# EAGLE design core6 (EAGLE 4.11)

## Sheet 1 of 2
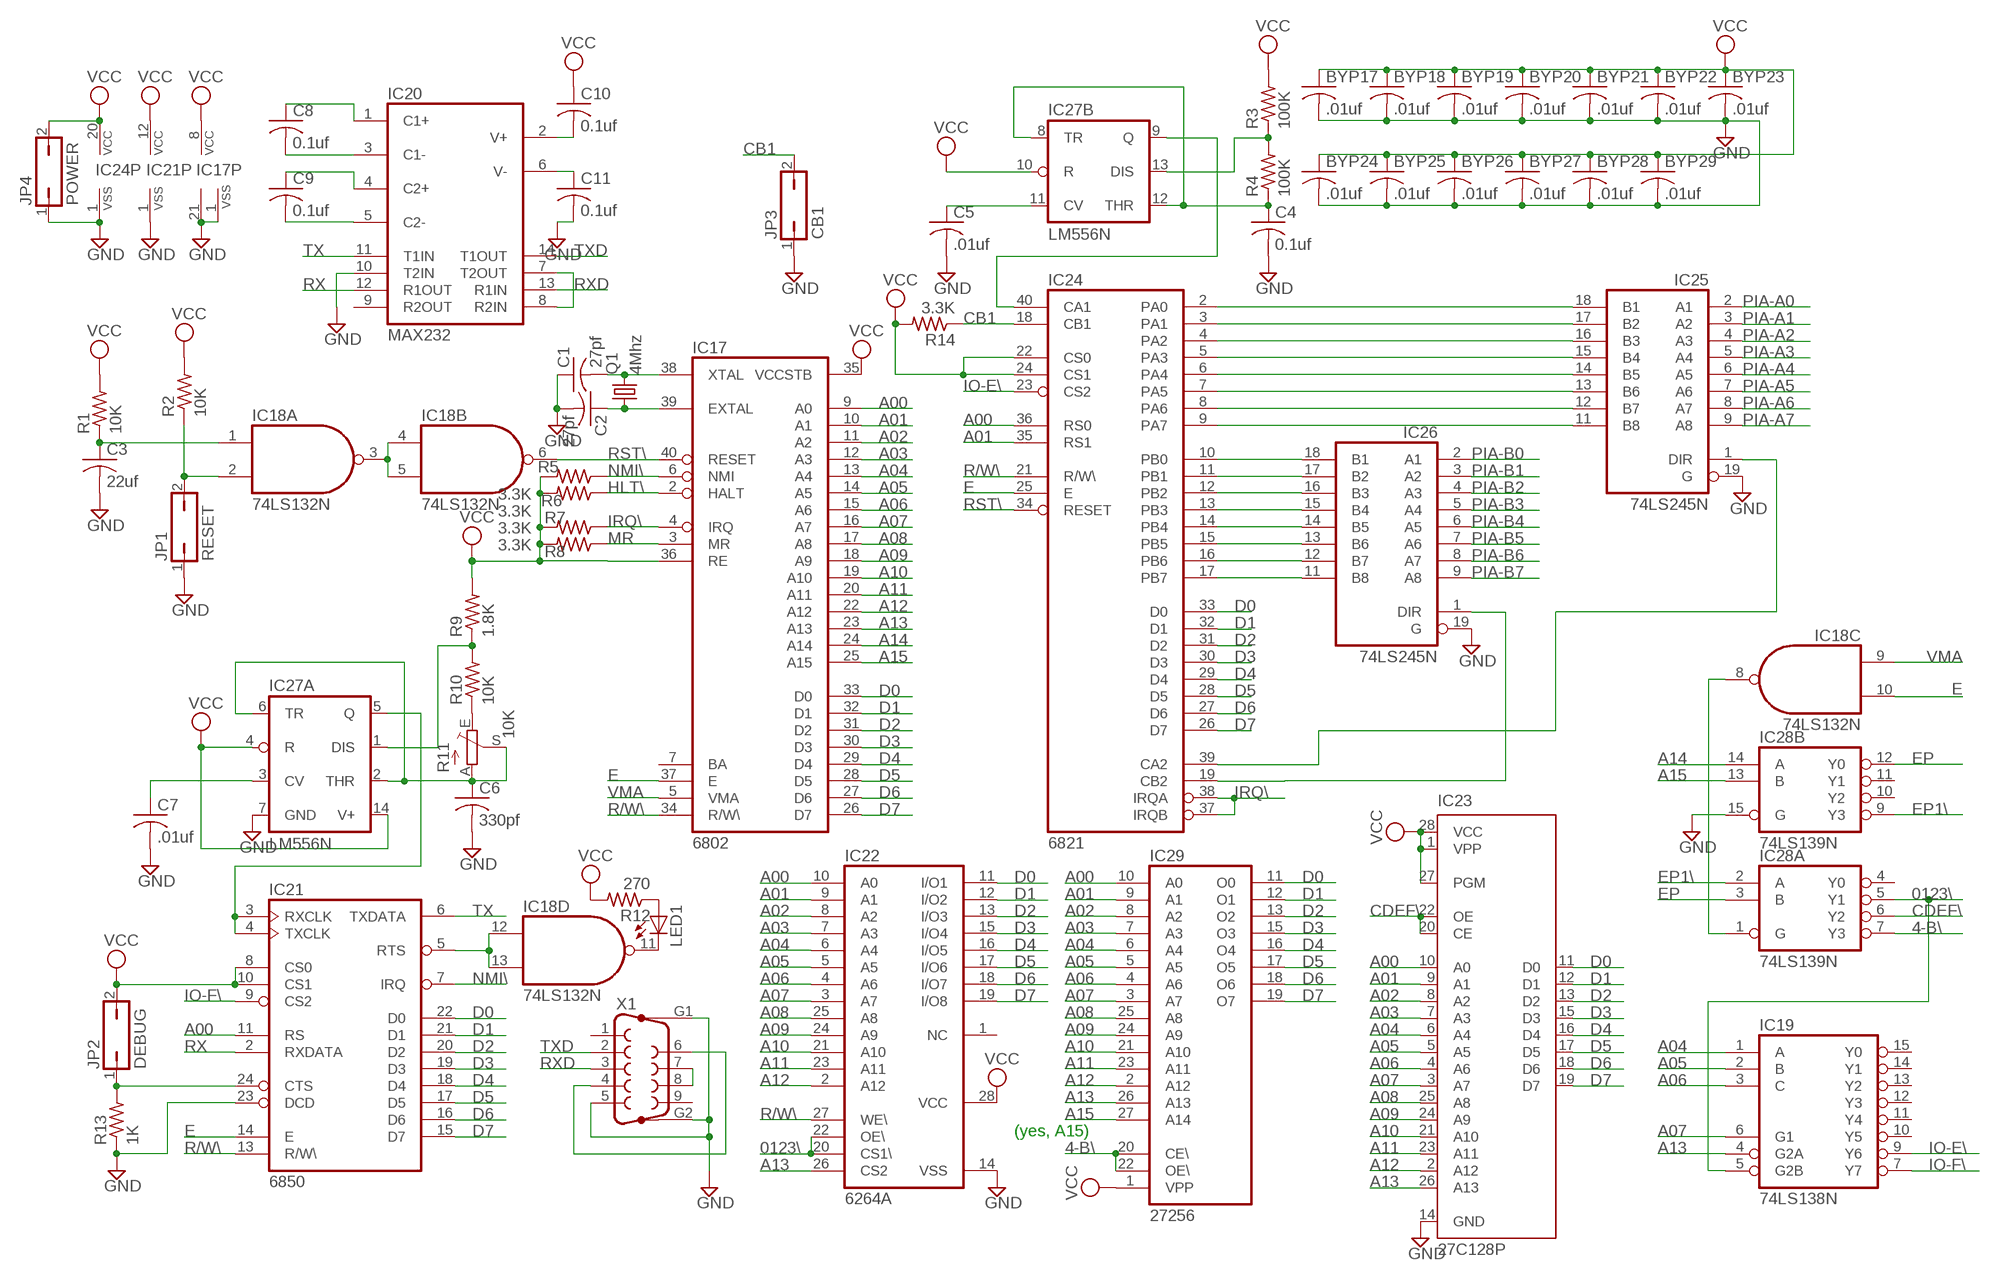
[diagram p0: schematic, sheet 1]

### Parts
BYP17  .01uf  C-US050-025X075  [C050-025X075]
BYP18  .01uf  C-US050-025X075  [C050-025X075]
BYP19  .01uf  C-US050-025X075  [C050-025X075]
BYP20  .01uf  C-US050-025X075  [C050-025X075]
BYP21  .01uf  C-US050-025X075  [C050-025X075]
BYP22  .01uf  C-US050-025X075  [C050-025X075]
BYP23  .01uf  C-US050-025X075  [C050-025X075]
BYP24  .01uf  C-US050-025X075  [C050-025X075]
BYP25  .01uf  C-US050-025X075  [C050-025X075]
BYP26  .01uf  C-US050-025X075  [C050-025X075]
BYP27  .01uf  C-US050-025X075  [C050-025X075]
BYP28  .01uf  C-US050-025X075  [C050-025X075]
BYP29  .01uf  C-US050-025X075  [C050-025X075]
C1  27pf  C-US050-025X075  [C050-025X075]
C2  27pf  C-US050-025X075  [C050-025X075]
C3  22uf  C-US102-043X133  [C102-043X133]
C4  0.1uf  C-US050-025X075  [C050-025X075]
C5  .01uf  C-US050-025X075  [C050-025X075]
C6  330pf  C-US050-025X075  [C050-025X075]
C7  .01uf  C-US050-025X075  [C050-025X075]
C8  0.1uf  C-US050-025X075  [C050-025X075]
C9  0.1uf  C-US050-025X075  [C050-025X075]
C10  0.1uf  C-US050-025X075  [C050-025X075]
C11  0.1uf  C-US050-025X075  [C050-025X075]
IC17  6802  [DIL40]
IC18  74LS132N  74LS00N  [DIL14]
IC19  74LS138N  [DIL16]
IC20  MAX232  [DIL16]
IC21  6850  [DIL24]
IC22  6264A  [DIL28-6]
IC23  27C128P  [DIL28-6]
IC24  6821  [DIL40]
IC25  74LS245N  [DIL20]
IC26  74LS245N  [DIL20]
IC27  LM556N  [DIL14]
IC28  74LS139N  [DIL16]
IC29  27256  [DIL28]
JP1  RESET  JP1Q  [JP1]
JP2  DEBUG  JP1Q  [JP1]
JP3  CB1  JP1Q  [JP1]
JP4  POWER  JP1Q  [JP1]
LED1  LED3MM  [LED3MM]
Q1  4Mhz  CRYTALHC18U-V  [HC18U-V]
R1  10K  R-US_0207/7  [0207/7]
R2  10K  R-US_0207/7  [0207/7]
R3  100K  R-US_0207/7  [0207/7]
R4  100K  R-US_0207/7  [0207/7]
R5  3.3K  R-US_0207/7  [0207/7]
R6  3.3K  R-US_0207/7  [0207/7]
R7  3.3K  R-US_0207/7  [0207/7]
R8  3.3K  R-US_0207/7  [0207/7]
R9  1.8K  R-US_0207/7  [0207/7]
R10  10K  R-US_0207/7  [0207/7]
R11  10K  TRIM_EU-B90P  [SP19L]
R12  270  R-US_0207/7  [0207/7]
R13  1K  R-US_0207/7  [0207/7]
R14  3.3K  R-US_0207/7  [0207/7]
X1  F09HP  [F09HP]

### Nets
4-B\: IC28.7(A:Y3) IC29.20(CE\) IC29.22(OE\)
0123\: IC19.5(G2B) IC22.20(CS1\) IC22.22(OE\) IC28.5(A:Y1)
A00: IC17.9(A0) IC21.11(RS) IC22.10(A0) IC23.10(A0) IC24.36(RS0) IC29.10(A0)
A01: IC17.10(A1) IC22.9(A1) IC23.9(A1) IC24.35(RS1) IC29.9(A1)
A02: IC17.11(A2) IC22.8(A2) IC23.8(A2) IC29.8(A2)
A03: IC17.12(A3) IC22.7(A3) IC23.7(A3) IC29.7(A3)
A04: IC17.13(A4) IC19.1(A) IC22.6(A4) IC23.6(A4) IC29.6(A4)
A05: IC17.14(A5) IC19.2(B) IC22.5(A5) IC23.5(A5) IC29.5(A5)
A06: IC17.15(A6) IC19.3(C) IC22.4(A6) IC23.4(A6) IC29.4(A6)
A07: IC17.16(A7) IC19.6(G1) IC22.3(A7) IC23.3(A7) IC29.3(A7)
A08: IC17.17(A8) IC22.25(A8) IC23.25(A8) IC29.25(A8)
A09: IC17.18(A9) IC22.24(A9) IC23.24(A9) IC29.24(A9)
A10: IC17.19(A10) IC22.21(A10) IC23.21(A10) IC29.21(A10)
A11: IC17.20(A11) IC22.23(A11) IC23.23(A11) IC29.23(A11)
A12: IC17.22(A12) IC22.2(A12) IC23.2(A12) IC29.2(A12)
A13: IC17.23(A13) IC19.4(G2A) IC22.26(CS2) IC23.26(A13) IC29.26(A13)
A14: IC17.24(A14) IC28.14(B:A)
A15: IC17.25(A15) IC28.13(B:B) IC29.27(A14)
CB1: IC24.18(CB1) JP3.2 R14.1
CDEF\: IC23.20(CE) IC23.22(OE) IC28.6(A:Y2)
D0: IC17.33(D0) IC21.22(D0) IC22.11(I/O1) IC23.11(D0) IC24.33(D0) IC29.11(O0)
D1: IC17.32(D1) IC21.21(D1) IC22.12(I/O2) IC23.12(D1) IC24.32(D1) IC29.12(O1)
D2: IC17.31(D2) IC21.20(D2) IC22.13(I/O3) IC23.13(D2) IC24.31(D2) IC29.13(O2)
D3: IC17.30(D3) IC21.19(D3) IC22.15(I/O4) IC23.15(D3) IC24.30(D3) IC29.15(O3)
D4: IC17.29(D4) IC21.18(D4) IC22.16(I/O5) IC23.16(D4) IC24.29(D4) IC29.16(O4)
D5: IC17.28(D5) IC21.17(D5) IC22.17(I/O6) IC23.17(D5) IC24.28(D5) IC29.17(O5)
D6: IC17.27(D6) IC21.16(D6) IC22.18(I/O7) IC23.18(D6) IC24.27(D6) IC29.18(O6)
D7: IC17.26(D7) IC21.15(D7) IC22.19(I/O8) IC23.19(D7) IC24.26(D7) IC29.19(O7)
E: IC17.37(E) IC18.10(C:I1) IC21.14(E) IC24.25(E)
EP: IC28.3(A:B) IC28.12(B:Y0)
EP1\: IC28.2(A:A) IC28.9(B:Y3)
GND [Power]: BYP17.2 BYP18.2 BYP19.2 BYP20.2 BYP21.2 BYP22.2 BYP23.2 BYP24.2 BYP25.2 BYP26.2 BYP27.2 BYP28.2 BYP29.2 C1.1 C2.2 C3.2 C4.2 C5.2 C6.2 C7.2 C11.2 IC17.1(VSS) IC17.21(VSS) IC20.10(T2IN) IC21.1(VSS) IC21.23(DCD) IC22.14(VSS) IC23.14(GND) IC24.1(VSS) IC25.19(G) IC26.19(G) IC27.7(A:GND) IC28.15(B:G) JP1.1 JP3.1 JP4.1 R13.1 X1.5 X1.G1 X1.G2 ; also sheet 2
HLT\: IC17.2(HALT) R5.1
IO-E\: IC19.9(Y6) IC24.23(CS2)
IO-F\: IC19.7(Y7) IC21.9(CS2)
IRQ\: IC17.4(IRQ) IC24.37(IRQB) IC24.38(IRQA) R7.1
MR: IC17.3(MR) R8.1
N$3: C2.1 IC17.39(EXTAL) Q1.1
N$4: C1.2 IC17.38(XTAL) Q1.2
N$5: IC24.2(PA0) IC25.18(B1)
N$6: IC18.3(A:O) IC18.4(B:I0) IC18.5(B:I1)
N$21: C3.1 IC18.1(A:I0) R1.1
N$22: IC18.2(A:I1) JP1.2 R2.1
N$23: IC21.3(RXCLK) IC21.4(TXCLK) IC27.5(A:Q)
N$24: IC24.10(PB0) IC26.18(B1)
N$25: IC24.11(PB1) IC26.17(B2)
N$27: C6.1 IC27.2(A:THR) IC27.6(A:TR) R11.A R11.S
N$28: IC27.1(A:DIS) R9.1 R10.2
N$94: IC24.12(PB2) IC26.16(B3)
N$124: IC24.13(PB3) IC26.15(B4)
N$125: IC24.14(PB4) IC26.14(B5)
N$126: IC24.15(PB5) IC26.13(B6)
N$127: IC24.16(PB6) IC26.12(B7)
N$128: IC24.17(PB7) IC26.11(B8)
N$129: IC24.3(PA1) IC25.17(B2)
N$130: IC24.4(PA2) IC25.16(B3)
N$131: IC24.5(PA3) IC25.15(B4)
N$132: IC24.6(PA4) IC25.14(B5)
N$133: IC24.7(PA5) IC25.13(B6)
N$134: IC24.8(PA6) IC25.12(B7)
N$135: IC24.9(PA7) IC25.11(B8)
N$136: IC24.19(CB2) IC26.1(DIR)
N$137: IC24.39(CA2) IC25.1(DIR)
N$138: IC24.40(CA1) IC27.9(B:Q)
N$140: C4.1 IC27.8(B:TR) IC27.12(B:THR) R4.1
N$141: IC27.13(B:DIS) R3.1 R4.2
N$142: C5.1 IC27.11(B:CV)
N$143: R10.1 R11.E
N$144: X1.4 X1.6
N$145: X1.7 X1.8
N$147: IC18.12(D:I0) IC18.13(D:I1) IC21.5(RTS)
N$148: IC18.11(D:O) LED1.K(C)
N$149: LED1.A R12.1
N$150: IC21.24(CTS) JP2.1 R13.2
N$151: IC18.8(C:O) IC28.1(A:G)
N$153: IC20.7(T2OUT) IC20.8(R2IN)
N$154: C7.1 IC27.3(A:CV)
N$155: C9.2 IC20.5(C2-)
N$156: C9.1 IC20.4(C2+)
N$157: C8.2 IC20.3(C1-)
N$158: C8.1 IC20.1(C1+)
N$159: C11.1 IC20.6(V-)
N$160: C10.2 IC20.2(V+)
NMI\: IC17.6(NMI) IC21.7(IRQ) R6.1
PIA-A0: IC25.2(A1) ; also sheet 2
PIA-A1: IC25.3(A2) ; also sheet 2
PIA-A2: IC25.4(A3) ; also sheet 2
PIA-A3: IC25.5(A4) ; also sheet 2
PIA-A4: IC25.6(A5) ; also sheet 2
PIA-A5: IC25.7(A6) ; also sheet 2
PIA-A6: IC25.8(A7) ; also sheet 2
PIA-A7: IC25.9(A8) ; also sheet 2
PIA-B0: IC26.2(A1) ; also sheet 2
PIA-B1: IC26.3(A2) ; also sheet 2
PIA-B2: IC26.4(A3) ; also sheet 2
PIA-B3: IC26.5(A4) ; also sheet 2
PIA-B4: IC26.6(A5) ; also sheet 2
PIA-B5: IC26.7(A6) ; also sheet 2
PIA-B6: IC26.8(A7) ; also sheet 2
PIA-B7: IC26.9(A8) ; also sheet 2
R/W\: IC17.34(R/W\) IC21.13(R/W\) IC22.27(WE\) IC24.21(R/W\)
RST\: IC17.40(RESET) IC18.6(B:O) IC24.34(RESET)
RX: IC20.12(R1OUT) IC21.2(RXDATA)
RXD: IC20.13(R1IN) X1.3
TX: IC20.11(T1IN) IC21.6(TXDATA)
TXD: IC20.14(T1OUT) X1.2
VCC [Power]: BYP17.1 BYP18.1 BYP19.1 BYP20.1 BYP21.1 BYP22.1 BYP23.1 BYP24.1 BYP25.1 BYP26.1 BYP27.1 BYP28.1 BYP29.1 C10.1 IC17.8(VCC) IC17.35(VCCSTB) IC17.36(RE) IC21.8(CS0) IC21.10(CS1) IC21.12(VCC) IC22.28(VCC) IC23.1(VPP) IC23.27(PGM) IC23.28(VCC) IC24.20(VCC) IC24.22(CS0) IC24.24(CS1) IC27.4(A:R) IC27.10(B:R) IC27.14(A:V+) IC29.1(VPP) JP2.2 JP4.2 R1.2 R2.2 R3.2 R5.2 R6.2 R7.2 R8.2 R9.2 R12.2 R14.2 ; also sheet 2
VMA: IC17.5(VMA) IC18.9(C:I0)
Unconnected: IC17.7(BA) IC19.10(Y5) IC19.11(Y4) IC19.12(Y3) IC19.13(Y2) IC19.14(Y1) IC19.15(Y0) IC20.9(R2OUT) IC22.1(NC) IC28.4(A:Y0) IC28.10(B:Y2) IC28.11(B:Y1) X1.1 X1.9

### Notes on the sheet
- (yes, A15)

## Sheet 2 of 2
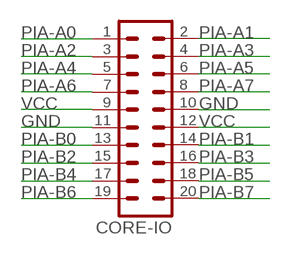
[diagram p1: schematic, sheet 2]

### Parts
CORE-IO  MA10-2  [MA10-2]

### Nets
GND [Power]: CORE-IO.10 CORE-IO.11 ; also sheet 1
PIA-A0: CORE-IO.1 ; also sheet 1
PIA-A1: CORE-IO.2 ; also sheet 1
PIA-A2: CORE-IO.3 ; also sheet 1
PIA-A3: CORE-IO.4 ; also sheet 1
PIA-A4: CORE-IO.5 ; also sheet 1
PIA-A5: CORE-IO.6 ; also sheet 1
PIA-A6: CORE-IO.7 ; also sheet 1
PIA-A7: CORE-IO.8 ; also sheet 1
PIA-B0: CORE-IO.13 ; also sheet 1
PIA-B1: CORE-IO.14 ; also sheet 1
PIA-B2: CORE-IO.15 ; also sheet 1
PIA-B3: CORE-IO.16 ; also sheet 1
PIA-B4: CORE-IO.17 ; also sheet 1
PIA-B5: CORE-IO.18 ; also sheet 1
PIA-B6: CORE-IO.19 ; also sheet 1
PIA-B7: CORE-IO.20 ; also sheet 1
VCC [Power]: CORE-IO.9 CORE-IO.12 ; also sheet 1

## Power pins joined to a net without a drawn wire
GND: IC18.7(P:GND) IC19.8(GND) IC20.15(GND) IC25.10(GND) IC26.10(GND) IC28.8(P:GND) IC29.14(GND)
VCC: IC18.14(P:VCC) IC19.16(VCC) IC20.16(VCC) IC25.20(VCC) IC26.20(VCC) IC28.16(P:VCC) IC29.28(VCC)

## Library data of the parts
BYP17-BYP29 C1-C11 = rcl:C-US: CAPACITOR, American symbol
CORE-IO = con-lstb:MA10-2: PIN HEADER
IC17 = micro-motorola:6802: MICROCONTROLLER/MEMORY DEVICE
IC18 = 74xx-us:74*00: Quad 2-input NAND gate
IC19 = 74xx-us:74*138: 3-line to 8-line DECODER/DEMULTIPLEXER
IC20 = maxim:MAX232: RS232 TRANSEIVER
IC21 = micro-motorola:6850: MICROCONTROLLER/MEMORY DEVICE
IC22 = memory-hitachi:6264A: MEMORY
IC23 = microchip:27*128: CMOS EPROM 128 K (16 K x 8)
IC24 = micro-motorola:6821: MICROCONTROLLER/MEMORY DEVICE
IC25 IC26 = 74xx-us:74*245: Octal BUS TRANSCEIVER, 3-state
IC27 = linear:*556: Dual TIMER
IC28 = 74xx-us:74*139: Dual 2-line to 4-line DECODER/DEMULTIPLEXER
IC29 = memory:27256: MEMORY
JP1-JP4 = jumper:JP1Q: JUMPER
LED1 = led:LED: LED
Q1 = crystal:CRYTAL: CRYSTAL
R1-R10 R12-R14 = rcl:R-US_: RESISTOR, American symbol
R11 = pot:TRIM_EU-: POTENTIOMETER
X1 = con-subd:F09HP: SUB-D

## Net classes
1 Power: width 0.508 mm, drill 0.254 mm, clearance 0.254 mm

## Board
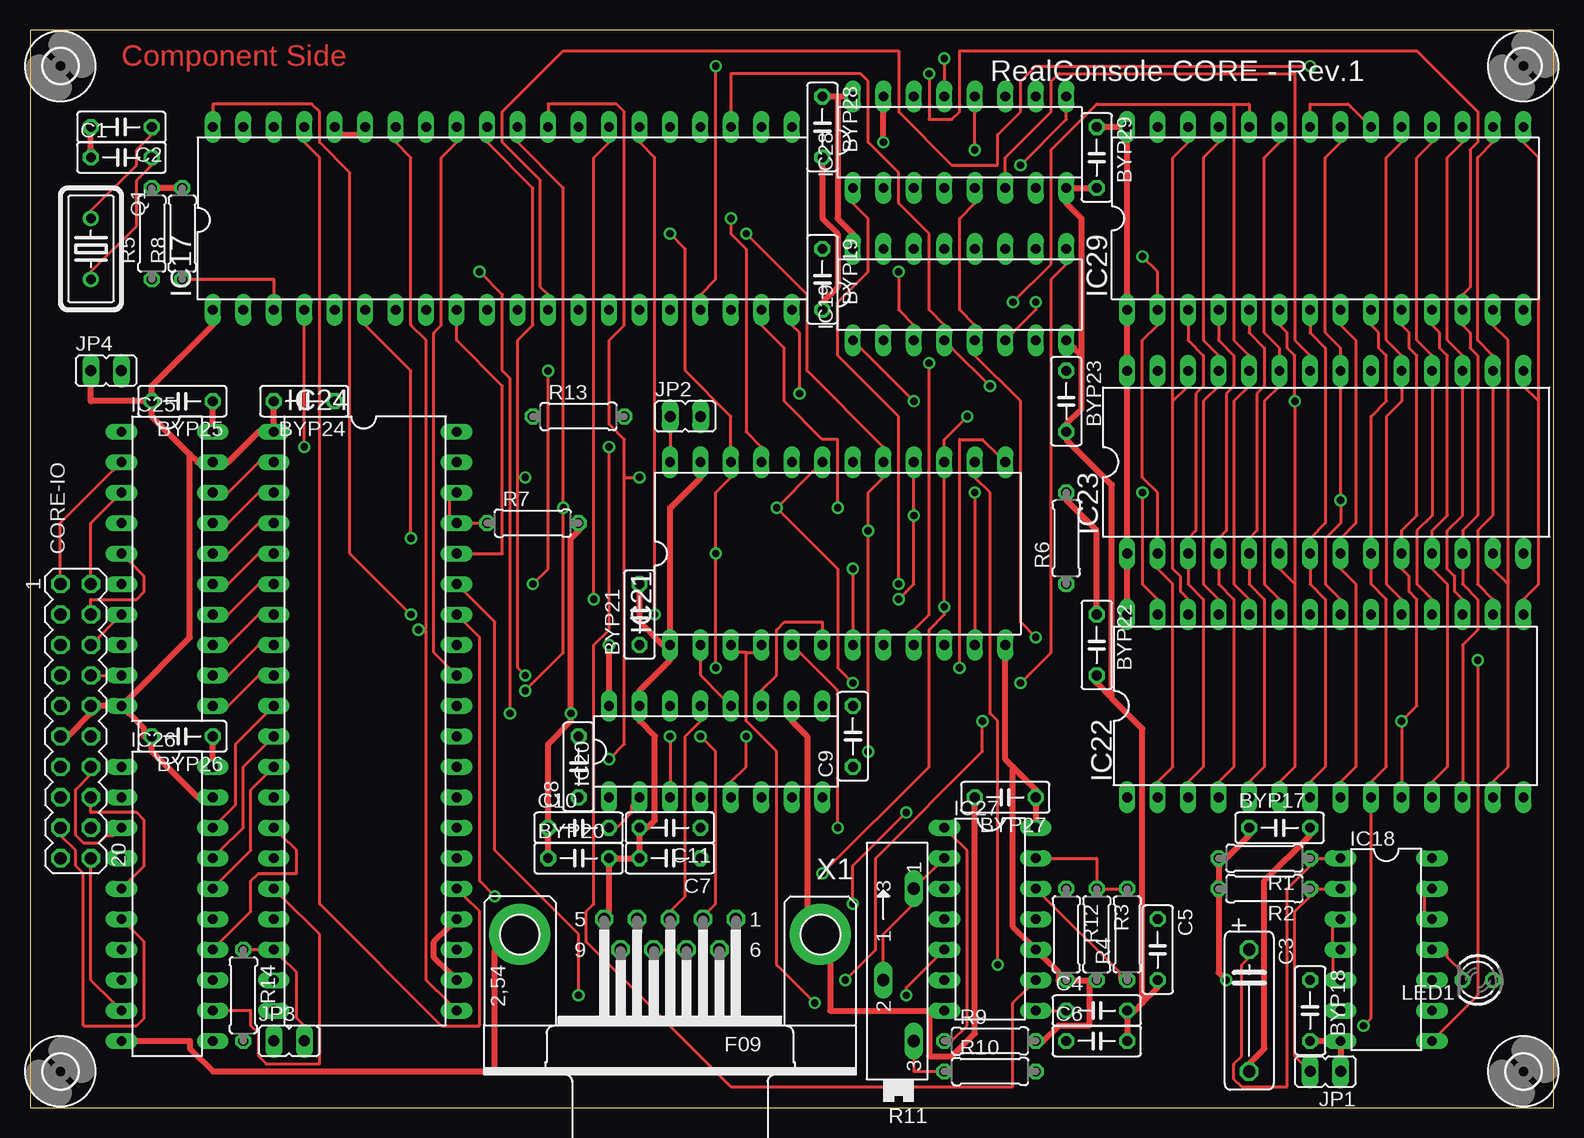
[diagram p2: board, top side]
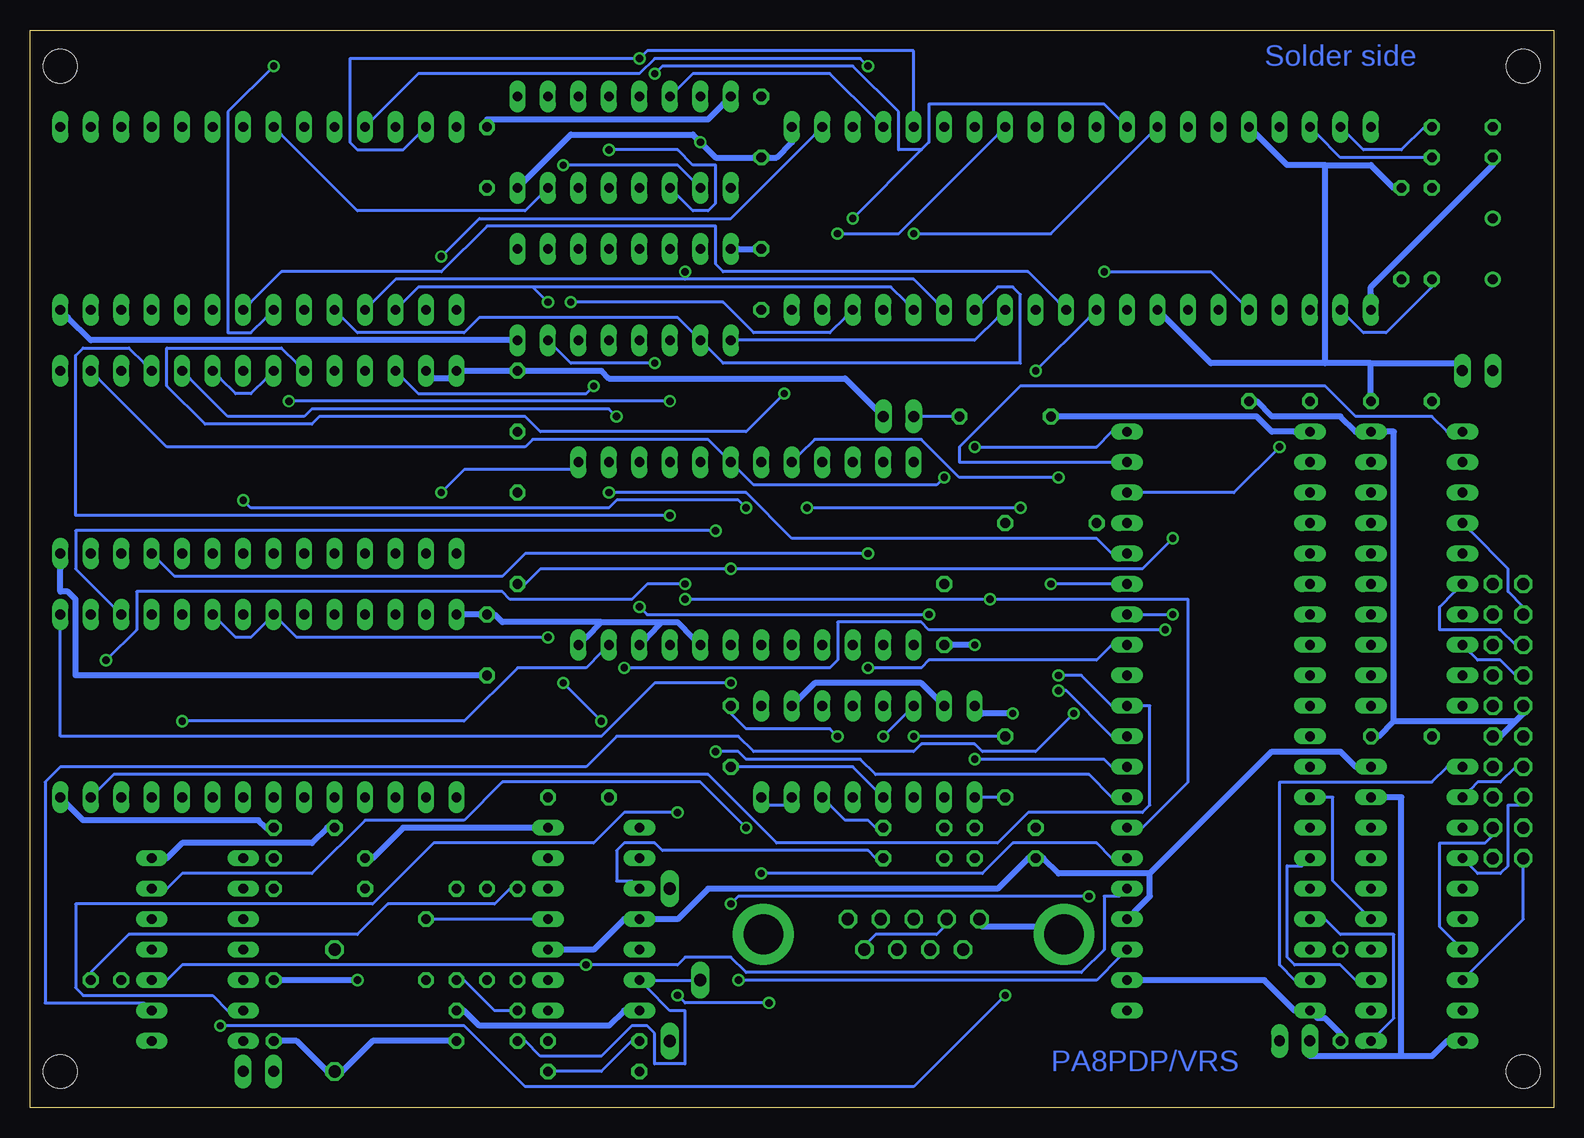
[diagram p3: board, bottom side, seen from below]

Size 126.98 x 89.84 mm. Coordinates in mm from the lower left corner, seen from the top.
Outline: 0,0 126.98,0 126.98,89.84 0,89.84 0,0
Copper layers (1*16): Top 0.035mm / dielectric 1.5mm / Bottom 0.035mm
Design rules "olimex10mil": minimum track width 10mil, minimum drill 24mil, track to track 10mil, track to pad 10mil, pad to pad 10mil, via to via 10mil, smd to smd 10mil, copper to edge 40mil, drill to drill 10mil, minimum pad ring 10mil, minimum via ring 8mil, stop-mask expansion 0mil, vias tented up to drill 0mil, thermal gap 10mil

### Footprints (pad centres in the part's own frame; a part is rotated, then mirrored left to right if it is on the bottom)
C050-025X075 = drill 0.813 octagon: 1 -2.54,0; 2 2.54,0
C102-043X133 = drill 1.016 octagon: 1 -5.08,0; 2 5.08,0
MA10-2 = drill 1.016 octagon: 1 -11.43,-1.27; 2 -11.43,1.27; 3 -8.89,-1.27; 4 -8.89,1.27; 5 -6.35,-1.27; 6 -6.35,1.27; 7 -3.81,-1.27; 8 -3.81,1.27; 9 -1.27,-1.27; 10 -1.27,1.27; 11 1.27,-1.27; 12 1.27,1.27; 13 3.81,-1.27; 14 3.81,1.27; 15 6.35,-1.27; 16 6.35,1.27; 17 8.89,-1.27; 18 8.89,1.27; 19 11.43,-1.27; 20 11.43,1.27
DIL40 = drill 0.813 long: 1 -24.13,-7.62; 2 -21.59,-7.62; 3 -19.05,-7.62; 4 -16.51,-7.62; 5 -13.97,-7.62; 6 -11.43,-7.62; 7 -8.89,-7.62; 8 -6.35,-7.62; 9 -3.81,-7.62; 10 -1.27,-7.62; 11 1.27,-7.62; 12 3.81,-7.62; 13 6.35,-7.62; 14 8.89,-7.62; 15 11.43,-7.62; 16 13.97,-7.62; 17 16.51,-7.62; 18 19.05,-7.62; 19 21.59,-7.62; 20 24.13,-7.62; 21 24.13,7.62; 22 21.59,7.62; 23 19.05,7.62; 24 16.51,7.62; 25 13.97,7.62; 26 11.43,7.62; 27 8.89,7.62; 28 6.35,7.62; 29 3.81,7.62; 30 1.27,7.62; 31 -1.27,7.62; 32 -3.81,7.62; 33 -6.35,7.62; 34 -8.89,7.62; 35 -11.43,7.62; 36 -13.97,7.62; 37 -16.51,7.62; 38 -19.05,7.62; 39 -21.59,7.62; 40 -24.13,7.62
DIL14 = drill 0.813 long: 1 -7.62,-3.81; 2 -5.08,-3.81; 3 -2.54,-3.81; 4 0,-3.81; 5 2.54,-3.81; 6 5.08,-3.81; 7 7.62,-3.81; 8 7.62,3.81; 9 5.08,3.81; 10 2.54,3.81; 11 0,3.81; 12 -2.54,3.81; 13 -5.08,3.81; 14 -7.62,3.81
DIL16 = drill 0.813 long: 1 -8.89,-3.81; 2 -6.35,-3.81; 3 -3.81,-3.81; 4 -1.27,-3.81; 5 1.27,-3.81; 6 3.81,-3.81; 7 6.35,-3.81; 8 8.89,-3.81; 9 8.89,3.81; 10 6.35,3.81; 11 3.81,3.81; 12 1.27,3.81; 13 -1.27,3.81; 14 -3.81,3.81; 15 -6.35,3.81; 16 -8.89,3.81
DIL24 = drill 0.813 long: 1 -13.97,-7.62; 2 -11.43,-7.62; 3 -8.89,-7.62; 4 -6.35,-7.62; 5 -3.81,-7.62; 6 -1.27,-7.62; 7 1.27,-7.62; 8 3.81,-7.62; 9 6.35,-7.62; 10 8.89,-7.62; 11 11.43,-7.62; 12 13.97,-7.62; 13 13.97,7.62; 14 11.43,7.62; 15 8.89,7.62; 16 6.35,7.62; 17 3.81,7.62; 18 1.27,7.62; 19 -1.27,7.62; 20 -3.81,7.62; 21 -6.35,7.62; 22 -8.89,7.62; 23 -11.43,7.62; 24 -13.97,7.62
DIL28-6 = drill 0.813 long: 1 -16.51,-7.62; 2 -13.97,-7.62; 3 -11.43,-7.62; 4 -8.89,-7.62; 5 -6.35,-7.62; 6 -3.81,-7.62; 7 -1.27,-7.62; 8 1.27,-7.62; 9 3.81,-7.62; 10 6.35,-7.62; 11 8.89,-7.62; 12 11.43,-7.62; 13 13.97,-7.62; 14 16.51,-7.62; 15 16.51,7.62; 16 13.97,7.62; 17 11.43,7.62; 18 8.89,7.62; 19 6.35,7.62; 20 3.81,7.62; 21 1.27,7.62; 22 -1.27,7.62; 23 -3.81,7.62; 24 -6.35,7.62; 25 -8.89,7.62; 26 -11.43,7.62; 27 -13.97,7.62; 28 -16.51,7.62
DIL20 = drill 0.813 long: 1 -11.43,-3.81; 2 -8.89,-3.81; 3 -6.35,-3.81; 4 -3.81,-3.81; 5 -1.27,-3.81; 6 1.27,-3.81; 7 3.81,-3.81; 8 6.35,-3.81; 9 8.89,-3.81; 10 11.43,-3.81; 11 11.43,3.81; 12 8.89,3.81; 13 6.35,3.81; 14 3.81,3.81; 15 1.27,3.81; 16 -1.27,3.81; 17 -3.81,3.81; 18 -6.35,3.81; 19 -8.89,3.81; 20 -11.43,3.81
DIL28 = drill 0.813 long: 1 -16.51,-7.62; 2 -13.97,-7.62; 3 -11.43,-7.62; 4 -8.89,-7.62; 5 -6.35,-7.62; 6 -3.81,-7.62; 7 -1.27,-7.62; 8 1.27,-7.62; 9 3.81,-7.62; 10 6.35,-7.62; 11 8.89,-7.62; 12 11.43,-7.62; 13 13.97,-7.62; 14 16.51,-7.62; 15 16.51,7.62; 16 13.97,7.62; 17 11.43,7.62; 18 8.89,7.62; 19 6.35,7.62; 20 3.81,7.62; 21 1.27,7.62; 22 -1.27,7.62; 23 -3.81,7.62; 24 -6.35,7.62; 25 -8.89,7.62; 26 -11.43,7.62; 27 -13.97,7.62; 28 -16.51,7.62
JP1 = drill 0.914 long: 1 0,-1.27; 2 0,1.27
LED3MM = drill 0.813 octagon: A -1.27,0; K 1.27,0
HC18U-V = drill 0.813 round: 1 -2.54,0; 2 2.54,0
0207/7 = drill 0.813 octagon: 1 -3.81,0; 2 3.81,0
SP19L = drill 1.016 long: A 5.715,-1.27; E -6.985,-1.27; S -1.905,1.27
2,8 = hole 2.8: 0,0
F09HP = drill 1.016 octagon: 1 -5.486,-1.27; 2 -2.743,-1.27; 3 0,-1.27; 4 2.743,-1.27; 5 5.486,-1.27; 6 -4.115,1.27; 7 -1.372,1.27; 8 1.372,1.27; 9 4.115,1.27 | drill 3.302 pad 5.08 round: G1 -12.522,0; G2 12.522,0

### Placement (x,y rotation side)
BYP17  104.14,23.33 0 top
BYP18  106.68,8.09 270 top
BYP19  66.04,69.05 270 top
BYP20  45.71,20.79 0 top
BYP21  50.79,41.11 90 top
BYP22  88.9,38.57 270 top
BYP23  86.36,58.89 270 top
BYP24  22.86,58.89 180 top
BYP25  12.69,58.89 180 top
BYP26  12.69,30.95 180 top
BYP27  81.28,25.87 180 top
BYP28  66.04,81.75 270 top
BYP29  88.9,79.21 270 top
C1  7.62,79.21 0 top
C2  7.62,81.75 180 top
C3  101.59,8.09 270 top
C4  88.9,8.09 0 top
C5  93.98,13.17 270 top
C6  88.9,5.55 0 top
C7  53.34,20.79 180 top
C8  45.71,28.41 90 top
C9  68.58,30.95 90 top
C10  45.71,23.33 0 top
C11  53.34,23.33 180 top
CORE-IO  3.81,32.22 270 top
IC17  39.36,74.13 0 top
IC18  113.03,13.17 270 top
IC19  77.47,67.78 0 top
IC20  57.14,29.68 0 top
IC21  67.31,46.19 0 top
IC22  107.95,33.49 0 top
IC23  107.95,53.81 0 top
IC24  27.94,32.22 270 top
IC25  11.42,44.92 270 top
IC26  11.42,16.98 270 top
IC27  80.01,15.71 270 top
IC28  77.47,80.48 0 top
IC29  107.95,74.13 0 top
JP1  107.95,3.01 90 top
JP2  54.6,57.62 270 top
JP3  21.59,5.55 270 top
JP4  6.34,61.43 270 top
LED1  120.65,10.63 180 top
Q1  5.08,71.59 270 top
R1  102.87,20.79 180 top
R2  102.87,18.25 180 top
R3  88.9,14.44 270 top
R4  91.44,14.44 90 top
R5  10.15,72.86 90 top
R6  86.36,47.46 90 top
R7  41.9,48.73 0 top
R8  12.69,72.86 90 top
R9  80.01,5.55 0 top
R10  80.01,3.01 0 top
R11  72.39,12.54 90 top
R12  86.36,14.44 270 top
R13  45.71,57.62 0 top
R14  17.78,9.36 270 top
U$3  [2,8]  2.54,86.83 0 top
U$4  [2,8]  2.54,3.01 0 top
U$5  [2,8]  124.45,86.83 0 top
U$6  [2,8]  124.45,3.01 0 top
X1  53.34,14.44 180 top

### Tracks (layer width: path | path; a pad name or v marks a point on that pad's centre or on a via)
4-B\
  Top 0.254: IC29.20 111.12,82.39 109.85,83.66 106.68,83.66 106.68,83.02 IC29.22
  Bottom 0.254: IC28.7 84.45,76.03 85.72,74.77 99.69,74.77 106.04,81.11 IC29.22
0123\  (via drill 0.61)
  Top 0.254: IC28.5 78.73,75.4 77.47,74.13 77.47,66.51 78.73,65.24 IC19.5 78.73,62.7 82.55,58.89 82.55,40.48 v83.81,39.2
  Bottom 0.254: IC22.20 111.12,40.48 109.85,39.2 108.58,39.2 107.31,40.48 IC22.22 106.04,40.48 104.77,39.2 v83.81,39.2
A00  (via drill 0.61)
  Top 0.254: IC24.36 36.82,46.19 39.36,46.19 39.36,60.16 35.55,63.97 35.55,65.24 IC17.9 | IC22.10 114.3,27.14 v114.3,32.22 115.56,33.49 115.56,42.38 114.93,43.02 114.93,44.28 114.3,44.92 IC23.10 114.3,47.46 114.3,48.09 115.56,49.37 115.56,62.7 114.93,63.34 114.93,64.61 114.3,65.24 IC29.10 | v78.73,51.27 78.73,39.84 IC21.11
  Bottom 0.254: v114.3,32.22 90.8,32.22 86.36,36.66 80.64,36.66 79.37,37.94 IC21.11 | v78.73,51.27 67.31,51.27 63.49,47.46 38.09,47.46 36.82,46.19 IC24.36
A01  (via drill 0.61)
  Top 0.254: v41.9,43.65 43.17,44.92 v43.17,61.43 | IC29.9 111.76,65.24 112.39,64.61 112.39,63.34 113.03,62.7 113.03,58.89 111.76,57.62 111.76,47.46 IC23.9 111.76,44.92 111.76,43.65 113.03,42.38 113.03,28.41 111.76,27.14 IC22.9 111.76,24.6 111.76,7.46 v111.12,6.82 | v45.71,9.36 45.71,14.44 38.73,21.42 38.73,40.48 36.19,43.02 IC24.35
  Bottom 0.254: v41.9,43.65 36.82,43.65 IC24.35 | v43.17,61.43 38.73,65.88 IC17.10 | v45.71,9.36 53.34,1.74 85.72,1.74 90.8,6.82 v111.12,6.82
A02
  Top 0.254: IC22.8 109.22,27.14 110.48,28.41 110.48,43.65 109.22,44.92 IC23.8 109.22,47.46 110.48,48.73 110.48,63.97 109.22,65.24 IC29.8
  Bottom 0.254: IC17.11 41.27,67.14 43.81,69.69 69.21,69.69 69.84,70.32 69.84,73.5 88.9,73.5 92.7,69.69 106.04,69.69 108.58,67.14 IC29.8
A03  (via drill 0.61)
  Top 0.254: IC22.7 106.68,27.14 107.95,28.41 107.95,42.38 106.68,43.65 106.68,44.92 IC23.7 106.68,47.46 107.95,48.73 107.95,63.34 106.68,64.61 106.68,65.24 IC29.7 | v106.68,86.83 83.81,86.83 82.55,85.56 82.55,83.02 80.64,81.11 80.64,78.58 76.83,78.58 72.39,83.02 72.39,88.1 44.45,88.1 39.36,83.02 39.36,80.48 42.54,77.3 42.54,68.41 43.17,67.78 IC17.12
  Bottom 0.254: v106.68,86.83 110.48,83.02 110.48,64.61 108.58,64.61 107.31,65.88 IC29.7
A04  (via drill 0.61)
  Top 0.254: 105.41,43.65 105.41,28.41 104.14,27.14 IC22.6 | 105.41,43.65 104.14,44.92 IC23.6 | 105.41,43.65 v105.41,58.89 105.41,62.7 104.77,63.34 104.77,64.61 104.14,65.24 IC29.6 | v73.66,58.89 69.21,63.34 IC19.1
  Bottom 0.254: IC17.13 46.35,65.88 48.25,63.97 67.94,63.97 IC19.1 | v73.66,58.89 v105.41,58.89
A05
  Top 0.254: IC22.5 101.59,27.14 102.87,28.41 102.87,42.38 101.59,43.65 101.59,44.92 IC23.5 101.59,47.46 102.23,48.09 102.23,59.52 102.87,60.16 102.87,63.34 101.59,64.61 101.59,65.24 IC29.5
  Bottom 0.254: IC29.5 100.96,65.88 99.69,64.61 90.8,64.61 89.53,65.88 73.02,65.88 71.75,64.61 IC19.2 70.48,63.34 69.21,62.06 44.45,62.06 44.45,67.78 45.08,68.41 46.35,68.41 47.62,67.14 IC17.14
A06  (via drill 0.61)
  Top 0.254: IC22.4 99.06,27.14 100.33,28.41 100.33,42.38 99.06,43.65 99.06,44.92 IC23.4 99.06,47.46 99.69,48.09 99.69,59.52 100.33,60.16 100.33,62.7 99.06,63.97 99.06,65.24 IC29.4 | v72.39,69.69 72.39,66.51 73.66,65.24 IC19.3
  Bottom 0.254: 72.39,69.05 96.52,69.05 98.42,67.14 IC29.4 | 72.39,69.05 53.34,69.05 51.43,67.14 IC17.15 | 72.39,69.05 v72.39,69.69
A07  (via drill 0.61)
  Top 0.254: IC22.3 96.52,27.14 97.79,28.41 97.79,42.38 96.52,43.65 96.52,44.92 IC23.3 96.52,47.46 97.15,48.09 97.15,59.52 97.79,60.16 97.79,62.7 96.52,63.97 96.52,65.24 IC29.3 | v83.81,67.14 83.81,66.51 81.91,64.61 IC19.6
  Bottom 0.254: 85.09,68.41 v83.81,67.14 | 85.09,68.41 94.61,68.41 95.88,67.14 IC29.3 | 85.09,68.41 55.24,68.41 53.97,67.14 IC17.16
A08  (via drill 0.61)
  Top 0.254: IC22.25 99.06,42.38 97.79,43.65 97.79,58.89 99.06,60.16 IC23.25 99.06,62.7 97.79,63.97 97.79,79.21 99.06,80.48 IC29.25 | v57.14,86.83 57.14,69.05 55.88,67.78 IC17.17
  Bottom 0.254: v57.14,86.83 57.78,87.47 74.93,87.47 76.2,86.19 94.61,86.19 98.42,82.39 IC29.25
A09  (via drill 0.61)
  Top 0.254: IC22.24 101.59,42.38 100.33,43.65 100.33,58.89 101.59,60.16 IC23.24 101.59,62.7 100.33,63.97 100.33,83.66 | v81.91,67.14 85.09,70.32 85.09,79.84 88.9,83.66 100.33,83.66 | 100.33,83.66 101.59,83.66 101.59,83.02 IC29.24
  Bottom 0.254: v81.91,67.14 69.21,67.14 66.67,64.61 60.32,64.61 59.05,65.88 IC17.18
A10  (via drill 0.61)
  Top 0.254: IC22.21 109.22,42.38 107.95,43.65 107.95,47.46 109.22,48.73 v109.22,50.63 109.22,60.16 IC23.21 109.22,62.7 109.22,63.34 107.95,64.61 107.95,79.21 109.22,80.48 IC29.21 | v67.31,50 67.31,55.71 66.04,55.71 62.86,58.89 62.86,63.34 60.95,65.24 IC17.19
  Bottom 0.254: v67.31,50 67.94,50.63 78.1,50.63 78.73,50 108.58,50 v109.22,50.63
A11  (via drill 0.61)
  Top 0.254: IC22.23 104.14,42.38 102.87,43.65 102.87,58.89 104.14,60.16 IC23.23 104.14,62.7 104.14,63.34 102.87,64.61 102.87,79.21 104.14,80.48 IC29.23 | v64.13,59.52 64.13,64.61 63.49,65.24 IC17.20
  Bottom 0.254: v64.13,59.52 67.31,56.35 84.45,56.35 85.72,57.62 102.87,57.62 103.5,56.98 112.39,56.98 115.56,60.16 115.56,63.34 106.04,63.34 104.77,62.06 IC23.23
A12  (via drill 0.61)
  Top 0.254: IC22.2 93.98,27.14 95.25,28.41 95.25,43.65 93.98,44.92 IC23.2 93.98,47.46 93.98,51.27 92.7,52.54 92.7,63.97 93.98,65.24 IC29.2 93.98,67.78 93.98,69.69 v92.7,70.95
  Bottom 0.254: v92.7,70.95 89.53,74.13 68.58,74.13 61.59,81.11 IC17.22
A13  (via drill 0.61)
  Top 0.254: IC17.23 58.41,83.02 58.41,86.19 69.21,86.19 69.84,85.56 69.84,80.48 72.39,77.94 72.39,75.4 74.93,72.86 74.93,66.51 76.2,65.24 IC19.4 76.83,63.34 v80.01,60.16 | 95.25,58.89 95.25,44.92 95.88,44.28 95.88,43.02 96.52,42.38 IC22.26 | 95.25,58.89 96.52,60.16 IC23.26 | 95.25,58.89 95.25,79.21 96.52,80.48 IC29.26
  Bottom 0.254: v80.01,60.16 80.64,59.52 94.61,59.52 95.88,60.8 IC23.26
A14
  Bottom 0.254: IC17.24 56.51,82.39 60.32,86.19 71.75,86.19 73.02,84.92 IC28.14
A15  (via drill 0.61)
  Top 0.254: v76.2,87.47 76.2,85.56 IC28.13
  Bottom 0.254: IC17.25 53.34,83.02 53.34,88.1 75.56,88.1 v76.2,87.47 100.33,87.47 100.33,80.48 99.69,79.84 95.88,79.84 94.61,81.11 IC29.27
CB1
  Top 0.254: R14.1 18.41,13.17 19.05,13.17 IC24.18 20.95,12.54 22.22,11.27 22.22,7.46 22.86,6.82 JP3.2
CDEF\
  Top 0.254: IC28.6 81.28,77.94 81.28,79.21 85.09,83.02 85.09,85.56 85.72,86.19 105.41,86.19 105.41,63.97 106.68,62.7 IC23.22
  Bottom 0.254: IC23.22 107.31,60.8 108.58,59.52 109.85,59.52 111.12,60.8 IC23.20
D0  (via drill 0.61)
  Top 0.254: IC22.11 116.84,27.14 118.11,28.41 118.11,43.65 116.84,44.92 IC23.11 116.84,47.46 116.84,48.09 118.11,49.37 118.11,62.7 117.47,63.34 117.47,64.61 116.84,65.24 IC29.11 | v57.14,36.66 v57.14,46.19 57.14,51.27 58.41,52.54 IC21.22 58.41,55.08 58.41,57.62 54.6,61.43 54.6,71.59 v53.34,72.86
  Bottom 0.254: v57.14,36.66 52.7,36.66 52.06,37.3 38.09,37.3 36.82,38.57 IC24.33 | v53.34,72.86 41.9,72.86 33.65,81.11 IC17.33 | v57.14,46.19 85.72,46.19 87.62,44.28 114.93,44.28 116.2,45.55 IC23.11
D1  (via drill 0.61)
  Top 0.254: IC22.12 119.38,27.14 119.38,38.57 120.65,39.84 120.65,42.38 119.38,43.65 119.38,44.92 IC23.12 119.38,47.46 119.38,48.09 120.65,49.37 120.65,62.7 120.01,63.34 120.01,64.61 119.38,65.24 IC29.12 119.38,67.78 120.01,68.41 120.01,79.84 120.65,80.48 120.65,83.02 115.56,88.1 77.47,88.1 77.47,83.02 76.83,82.39 74.93,82.39 v74.93,86.19 | IC24.32 34.92,36.66 33.65,37.94 33.65,64.61 34.28,65.24 34.28,79.21 35.55,80.48 IC17.32 | v58.41,74.13 58.41,72.86 59.68,71.59 59.68,56.35 60.95,55.08 IC21.21
  Bottom 0.254: 52.7,79.84 52.06,80.48 52.06,83.66 37.46,83.66 36.19,82.39 IC17.32 | 52.7,79.84 v58.41,74.13 | v74.93,86.19 74.29,86.83 58.41,86.83 54.6,83.02 54.6,79.84 52.7,79.84
D2  (via drill 0.61)
  Top 0.254: 123.19,43.65 123.19,28.41 121.92,27.14 IC22.13 | 123.19,43.65 121.92,44.92 IC23.13 | 123.19,43.65 123.19,63.97 121.92,65.24 IC29.13 | v41.27,36.03 40.63,36.66 40.63,52.54 | 40.63,52.54 40.63,63.97 41.9,65.24 41.9,76.67 38.09,80.48 IC17.31 | 40.63,52.54 v41.27,52.54
  Bottom 0.254: v41.27,36.03 39.36,36.03 36.82,33.49 IC24.31 34.28,33.49 33.65,33.49 33.65,25.23 34.28,24.6 43.81,24.6 46.35,22.06 64.77,22.06 70.48,27.77 120.01,27.77 121.28,26.5 IC22.13 | v41.27,52.54 49.52,52.54 52.7,55.71 61.59,55.71 62.86,54.45 IC21.20
D3  (via drill 0.61)
  Top 0.254: 125.73,58.89 125.73,43.65 124.45,42.38 IC22.15 | 125.73,58.89 124.45,60.16 IC23.15 | 125.73,58.89 125.73,79.21 124.45,80.48 IC29.15 | v41.27,34.76 44.45,37.94 v44.45,50 44.45,76.67 40.63,80.48 IC17.30 | IC21.19 65.4,53.17 v62.22,50 67.31,44.92 67.31,36.66 v68.58,35.39
  Bottom 0.254: v41.27,34.76 40.63,34.76 36.82,30.95 IC24.30 | v44.45,50 v62.22,50 | v68.58,35.39 74.93,35.39 79.37,30.95 124.45,30.95 124.45,39.84 IC22.15
D4  (via drill 0.61)
  Top 0.254: v48.25,29.04 49.52,30.31 49.52,52.54 | 49.52,52.54 49.52,55.71 48.25,56.98 48.25,63.97 49.52,65.24 49.52,83.02 48.89,83.66 43.17,83.66 43.17,83.02 IC17.29 | IC22.16 121.92,42.38 120.65,43.65 120.65,48.09 121.92,49.37 121.92,60.16 IC23.16 121.92,62.7 120.65,63.97 120.65,79.21 121.92,80.48 IC29.16 | 49.52,52.54 v50.79,52.54
  Bottom 0.254: v48.25,29.04 37.46,29.04 36.82,28.41 IC24.29 | IC23.16 121.28,60.8 115.56,55.08 85.72,55.08 85.09,55.71 70.48,55.71 69.21,54.45 IC21.18 67.94,53.17 66.67,51.91 51.43,51.91 v50.79,52.54
D5  (via drill 0.61)
  Top 0.254: IC22.17 119.38,42.38 118.74,43.02 118.74,44.28 118.11,44.92 118.11,48.09 119.38,49.37 119.38,60.16 IC23.17 119.38,62.7 118.11,63.97 118.11,79.21 119.38,80.48 IC29.17 | v69.84,29.68 v69.84,48.09 69.84,51.27 71.12,52.54 IC21.17 71.12,55.08 64.77,61.43 64.77,67.78 v59.68,72.86
  Bottom 0.254: v69.84,29.68 67.94,29.68 67.31,29.04 57.78,29.04 56.51,27.77 38.73,27.77 36.82,25.87 IC24.28 | v59.68,72.86 54.6,72.86 46.35,81.11 IC17.28 | v69.84,48.09 123.19,48.09 123.19,44.92 120.01,41.74 IC22.17
D6  (via drill 0.61)
  Top 0.254: IC22.18 116.84,42.38 115.56,43.65 115.56,48.09 116.84,49.37 116.84,60.16 IC23.18 116.84,62.7 115.56,63.97 115.56,79.21 116.84,80.48 IC29.18 | v72.39,42.38 73.66,43.65 v73.66,49.37 73.66,52.54 IC21.16 | v46.98,42.38 46.98,79.21 48.25,80.48 IC17.27
  Bottom 0.254: v72.39,42.38 v46.98,42.38 30.48,42.38 30.48,27.14 34.28,23.33 IC24.27 | v73.66,49.37 123.19,49.37 123.19,62.7 122.55,63.34 118.74,63.34 117.47,62.06 IC23.18
D7  (via drill 0.61)
  Top 0.254: IC22.19 114.3,42.38 113.03,43.65 113.03,57.62 114.3,58.89 114.3,60.16 IC23.19 114.3,62.7 113.03,63.97 113.03,79.21 114.3,80.48 IC29.19 | v66.04,19.52 74.93,28.41 74.93,39.84 76.2,41.11 v76.2,41.74 76.2,52.54 IC21.15 76.2,55.08 76.2,55.71 v78.1,57.62 | v52.06,41.11 52.06,79.21 50.79,80.48 IC17.26
  Bottom 0.254: v66.04,19.52 47.62,19.52 45.08,22.06 38.09,22.06 36.82,20.79 IC24.26 | v52.06,41.11 75.56,41.11 v76.2,41.74 | v78.1,57.62 78.73,58.25 103.5,58.25 104.14,57.62 110.48,57.62 113.66,60.8 IC23.19
E  (via drill 0.61)
  Top 0.254: IC17.37 22.86,80.48 24.12,79.21 24.12,16.98 34.28,6.82 37.46,6.82 37.46,16.34 36.19,17.61 IC24.25 | v80.64,11.9 80.64,32.22 80.01,32.85 80.01,51.27 78.73,52.54 IC21.14
  Bottom 0.254: IC18.10 115.56,10.63 114.3,11.9 v80.64,11.9 73.02,11.9 72.39,12.54 68.58,12.54 67.31,11.27 39.36,11.27 37.46,13.17 37.46,17.61 36.19,17.61 IC24.25
EP  (via drill 0.61)
  Top 0.254: v78.73,79.84 78.73,83.02 IC28.12
  Bottom 0.254: v78.73,79.84 73.02,79.84 71.75,78.58 69.84,78.58 69.84,75.4 70.48,74.77 71.75,74.77 73.02,76.03 IC28.3
EP1\  (via drill 0.61)
  Top 0.254: v82.55,78.58 86.36,82.39 86.36,83.02 IC28.9
  Bottom 0.254: v82.55,78.58 73.02,78.58 71.75,77.3 IC28.2
GND  (via drill 0.61)
  Top 0.508: IC25.10 6.34,33.49 5.71,33.49 CORE-IO.10 5.08,32.85 3.17,30.95 CORE-IO.11 | IC26.19 13.96,25.87 10.15,29.68 10.15,30.31 BYP26.2 9.52,30.95 9.52,31.58 8.25,32.85 IC25.10 | BYP24.2 20.32,58.25 20.32,56.98 IC24.1 19.05,56.35 16.51,53.81 IC25.19 13.96,53.81 13.33,54.45 | C1.1 5.08,79.84 5.08,81.11 C2.2 | BYP25.2 9.52,58.89 5.08,58.89 5.08,60.16 JP4.1 | IC17.1 15.23,65.24 10.15,60.16 10.15,59.52 BYP25.2 | 13.33,54.45 10.15,57.62 10.15,58.25 BYP25.2 | 13.33,54.45 13.33,39.2 8.25,34.12 IC25.10 | BYP19.2 66.04,67.14 67.31,68.41 67.31,72.86 66.04,74.13 66.04,78.58 BYP28.2 | v71.12,80.48 71.12,83.02 IC28.15 | BYP29.2 88.26,76.67 86.99,76.67 IC28.8 86.36,75.4 87.62,74.13 87.62,62.7 | 87.62,62.7 87.62,58.25 86.36,56.98 BYP23.2 86.36,55.71 90.17,51.91 90.17,34.12 | 87.62,62.7 86.99,63.34 IC19.8 | BYP18.2 107.31,5.55 107.95,5.55 IC18.7 109.22,4.92 109.22,4.28 JP1.1 | C6.2 91.44,6.18 91.44,7.46 C4.2 92.07,8.09 92.7,8.73 | 92.7,8.73 93.98,10 C5.2 | 90.17,34.12 92.7,31.58 92.7,8.73 | 90.17,34.12 88.9,35.39 BYP22.2 | BYP17.2 106.68,22.7 102.87,18.88 102.87,4.92 101.59,3.64 C3.2 | 74.93,8.09 66.67,8.09 66.67,12.54 X1.G1 64.77,16.34 64.77,30.95 63.49,32.22 IC20.10 | 74.93,8.09 IC27.7 74.93,8.09 | 74.93,8.09 74.93,4.28 76.83,4.28 78.73,6.18 78.73,25.23 BYP27.2 | IC21.1 53.34,37.3 50.79,34.76 IC20.15 50.79,32.22 52.06,30.95 52.06,23.96 51.43,23.33 C11.2 50.79,22.7 50.79,21.42 C7.2 50.16,20.79 48.89,20.79 BYP20.2 48.25,20.15 48.25,16.34 X1.5 | BYP21.2 50.79,43.02 50.79,40.48 52.7,38.57 IC21.1 | IC21.23 55.88,52.54 53.34,50 53.34,39.84 IC21.1 | IC26.10 8.88,5.55 13.33,5.55 13.33,4.92 15.23,3.01 38.73,3.01 38.73,13.17 X1.G2
  Bottom 0.508: 12.69,4.28 20.32,4.28 JP3.1 | 12.69,4.28 10.15,4.28 8.88,5.55 IC26.10 | 12.69,4.28 12.69,25.87 13.96,25.87 IC26.19 | R13.1 41.27,57.62 24.76,57.62 23.49,56.35 21.59,56.35 IC24.1 | C1.1 5.08,78.58 15.23,68.41 15.23,67.78 IC17.1 | IC17.21 63.49,80.48 64.77,79.21 65.4,79.21 BYP28.2 66.67,79.21 69.84,79.21 v71.12,80.48 71.75,81.11 81.91,81.11 85.72,77.3 IC28.8 | IC29.14 123.82,65.88 121.92,63.97 86.99,63.97 IC19.8 | BYP17.2 107.31,23.33 107.95,23.96 122.55,23.96 123.82,25.23 IC22.14 | BYP18.2 106.04,5.55 104.77,5.55 102.23,3.01 C3.2 100.96,3.01 98.42,5.55 92.07,5.55 C6.2 | IC23.14 124.45,44.92 124.45,43.02 123.82,43.02 123.19,42.38 123.19,36.03 89.53,36.03 BYP22.2 | X1.5 47.62,15.08 43.17,15.08 X1.G2 | IC20.10 62.86,34.12 61.59,35.39 52.7,35.39 51.43,34.12 IC20.15 | C4.2 90.8,8.09 89.53,6.82 78.73,6.82 77.47,8.09 IC27.7
HLT\
  Bottom 0.254: R5.1 10.15,68.41 13.96,64.61 15.87,64.61 17.14,65.88 IC17.2
IO-E\  (via drill 0.61)
  Top 0.254: v67.94,10.63 70.48,13.17 70.48,20.79 79.37,29.68 v79.37,32.22 | v82.55,35.39 85.09,37.94 85.09,69.05 86.36,70.32 IC19.9
  Bottom 0.254: v67.94,10.63 38.09,10.63 36.19,12.54 IC24.23 | v79.37,32.22 v82.55,35.39
IO-F\  (via drill 0.61)
  Top 0.254: v74.93,62.06 74.93,41.11 73.66,39.84 IC21.9
  Bottom 0.254: v74.93,62.06 81.91,62.06 83.18,63.34 IC19.7
IRQ\  (via drill 0.61)
  Top 0.254: R7.1 37.46,48.73 36.82,48.73 IC24.37 34.92,49.37 34.92,50.63 IC24.38 | v22.86,55.08 22.86,65.24 IC17.4
  Bottom 0.254: v22.86,55.08 26.67,51.27 34.28,51.27 IC24.38
MR
  Top 0.254: R8.1 13.33,69.05 20.32,69.05 20.32,67.78 IC17.3
N$3
  Top 0.254: Q1.1 5.08,74.77 8.88,78.58 8.88,79.84 10.15,81.11 C2.1
  Bottom 0.254: IC17.39 17.14,81.11 15.87,79.84 12.69,79.84 10.79,81.75 C2.1
N$4
  Top 0.254: Q1.2 5.08,69.69 8.88,73.5 8.88,77.3 10.15,78.58 C1.2
  Bottom 0.254: IC17.38 19.68,81.11 17.78,79.21 10.79,79.21 C1.2
N$5
  Top 0.254: IC25.18 16.51,51.27 19.05,53.81 IC24.2
N$6
  Top 0.254: IC18.5 108.58,11.27 108.58,12.54 IC18.4 108.58,13.81 108.58,15.08 IC18.3
N$21
  Top 0.254: IC18.1 107.95,20.79 107.31,20.79 R1.1 106.68,20.15 104.77,18.25 104.77,1.74 100.96,1.74 100.33,2.38 100.33,3.64 100.96,4.28 100.96,11.9 101.59,12.54 C3.1
N$22
  Top 0.254: IC18.2 107.95,18.25 107.31,18.25 R2.1 106.68,17.61 105.41,16.34 105.41,4.28 106.04,3.64 JP1.2
N$23  (via drill 0.61)
  Top 0.254: 59.68,37.94 60.32,37.94 IC21.4 | 59.68,37.94 59.05,37.94 IC21.3 | v73.02,9.36 73.02,10 75.56,12.54 IC27.5 | v65.4,8.73 62.22,11.9 62.22,29.68 59.68,32.22 59.68,37.94
  Bottom 0.254: v73.02,9.36 72.39,8.73 v65.4,8.73
N$24
  Top 0.254: IC26.18 15.87,23.96 17.14,25.23 17.14,30.31 19.68,32.85 IC24.10
N$25
  Top 0.254: IC26.17 15.87,21.42 17.78,23.33 17.78,28.41 19.68,30.31 IC24.11
N$27
  Top 0.254: IC27.2 75.56,20.15 74.29,18.88 R11.A 73.66,16.98 71.12,14.44 71.12,11.9 R11.S
  Bottom 0.254: R11.S 71.75,10.63 74.93,10.63 IC27.6 75.56,10 73.66,8.09 72.39,8.09 72.39,3.64 74.93,3.64 74.93,6.18 75.56,6.82 76.83,6.82 79.37,4.28 84.45,4.28 85.72,5.55 C6.1
N$28
  Top 0.254: IC27.1 76.83,22.7 78.1,21.42 78.1,6.82 76.83,5.55 R9.1
  Bottom 0.254: R9.1 76.83,5.55 79.37,3.01 83.18,3.01 R10.2
N$94
  Top 0.254: IC26.16 15.87,18.88 18.41,21.42 18.41,26.5 19.68,27.77 IC24.12
N$124
  Bottom 0.254: IC26.15 15.87,16.34 18.41,18.88 18.41,25.87 19.05,25.87 IC24.13
N$125
  Top 0.254: IC26.14 15.87,13.81 18.41,16.34 18.41,18.88 19.05,19.52 22.22,19.52 22.22,21.42 20.95,22.7 IC24.14
N$126
  Bottom 0.254: IC26.13 16.51,10.63 17.78,11.9 21.59,11.9 22.22,12.54 22.22,20.15 20.95,20.15 IC24.15
N$127
  Top 0.254: IC26.12 16.51,8.09 18.41,8.09 18.41,6.82 19.05,6.18 19.05,4.28 19.68,3.64 24.12,3.64 24.12,14.44 20.95,17.61 IC24.16
N$128
  Bottom 0.254: IC26.11 14.6,6.18 13.33,7.46 13.33,14.44 17.78,14.44 19.05,15.71 IC24.17
N$129
  Top 0.254: IC25.17 16.51,48.73 19.05,51.27 IC24.3
N$130
  Top 0.254: IC25.16 16.51,46.19 19.05,48.73 IC24.4
N$131
  Top 0.254: IC25.15 16.51,43.65 19.05,46.19 IC24.5
N$132
  Top 0.254: IC25.14 16.51,41.11 19.05,43.65 IC24.6
N$133
  Top 0.254: IC25.13 16.51,38.57 19.05,41.11 IC24.7
N$134
  Top 0.254: IC25.12 16.51,36.03 19.05,38.57 IC24.8
N$135
  Top 0.254: IC25.11 16.51,33.49 19.05,36.03 IC24.9
N$136
  Bottom 0.254: IC24.19 21.59,10.63 22.86,11.9 22.86,27.14 10.15,27.14 8.88,28.41 IC26.1
N$137
  Bottom 0.254: IC25.1 8.88,56.35 10.15,57.62 16.51,57.62 19.05,60.16 44.45,60.16 49.52,55.08 49.52,53.81 36.82,53.81 IC24.39
N$138  (via drill 0.61)
  Top 0.254: v48.25,55.08 48.25,39.84 46.98,38.57 46.98,16.98 46.35,16.34 46.35,13.81 58.41,1.74 81.91,1.74 81.91,8.73 83.18,10 IC27.9
  Bottom 0.254: v48.25,55.08 38.09,55.08 36.82,56.35 IC24.40
N$140
  Top 0.254: IC27.8 85.09,8.09 85.72,8.09 C4.1 | IC27.12 84.45,17.61 90.8,11.27 90.8,10.63 R4.1
  Bottom 0.254: R4.1 90.8,10.63 88.26,8.09 86.99,8.09 C4.1
N$141
  Top 0.254: R4.2 90.8,18.25 89.53,18.25 R3.1 88.9,18.88 88.9,20.79 85.09,20.79 IC27.13
N$142
  Bottom 0.254: IC27.11 85.09,15.71 93.34,15.71 C5.1
N$143
  Top 0.254: R10.1 75.56,3.01 73.66,3.01 73.66,4.28 R11.E
N$144
  Bottom 0.254: X1.4 50.79,15.08 51.43,14.44 56.51,14.44 57.14,13.81 X1.6
N$145
  Top 0.254: X1.8 52.7,13.17 53.97,13.17 X1.7
N$147  (via drill 0.61)
  Top 0.254: IC18.12 116.2,16.34 116.2,17.61 IC18.13 | v67.31,23.33 67.31,34.76 64.13,37.94 IC21.5
  Bottom 0.254: v67.31,23.33 71.12,27.14 87.62,27.14 90.8,23.96 99.06,23.96 103.5,19.52 114.3,19.52 115.56,18.25 IC18.13
N$148
  Top 0.254: LED1.K 119.38,11.27 118.11,12.54 118.11,13.17 IC18.11
N$149
  Bottom 0.254: R12.1 86.99,18.25 88.26,16.98 97.15,16.98 99.69,14.44 118.74,14.44 121.92,11.27 LED1.A
N$150
  Top 0.254: IC21.24 53.34,55.08 53.34,56.35 JP2.1
  Bottom 0.254: R13.2 50.16,57.62 52.7,57.62 JP2.1
N$151  (via drill 0.61)
  Top 0.254: v120.65,37.3 120.65,9.36 117.47,6.18 IC18.8 | v72.39,43.65 72.39,57.62 67.31,62.7 67.31,67.14 69.84,69.69 69.84,74.13 68.58,75.4 IC28.1
  Bottom 0.254: v120.65,37.3 118.11,39.84 118.11,43.02 87.62,43.02 86.99,42.38 76.83,42.38 75.56,43.65 v72.39,43.65
N$153
  Bottom 0.254: IC20.7 64.13,25.23 65.4,25.23 IC20.8
N$154
  Bottom 0.254: C7.1 56.51,20.79 57.14,21.42 74.29,21.42 74.93,22.06 77.47,22.06 78.1,21.42 78.1,18.88 76.83,18.88 IC27.3
N$155  (via drill 0.61)
  Top 0.254: v59.68,30.95 59.68,28.41 58.41,27.14 IC20.5
  Bottom 0.254: v59.68,30.95 60.32,31.58 67.31,31.58 68.58,32.85 C9.2
N$156
  Bottom 0.254: IC20.4 56.51,26.5 58.41,28.41 67.94,28.41 C9.1
N$157  (via drill 0.61)
  Top 0.254: v53.34,30.95 53.34,27.14 IC20.3
  Bottom 0.254: v53.34,30.95 46.35,30.95 C8.2
N$158
  Bottom 0.254: C8.1 46.35,25.87 47.62,25.87 IC20.1
N$159
  Bottom 0.254: C11.1 56.51,23.33 57.14,23.96 59.05,23.96 60.32,25.23 IC20.6
N$160
  Top 0.254: C10.2 48.89,23.33 50.16,24.6 50.16,25.23 IC20.2
NMI\  (via drill 0.61)
  Top 0.254: v31.75,47.46 31.75,61.43 27.94,65.24 IC17.6 | v68.58,44.92 68.58,39.84 IC21.7
  Bottom 0.254: v31.75,47.46 34.28,44.92 v68.58,44.92 84.45,44.92 85.72,43.65 R6.1
PIA-A0
  Top 0.254: IC25.2 6.98,53.17 2.54,48.73 2.54,44.28 CORE-IO.1
PIA-A1
  Top 0.254: IC25.3 6.98,50.63 5.08,48.73 5.08,44.28 CORE-IO.2
PIA-A2
  Bottom 0.254: IC25.4 6.98,48.09 3.81,44.92 3.81,43.02 2.54,41.74 CORE-IO.3
PIA-A3
  Top 0.254: IC25.5 8.25,45.55 9.52,44.28 9.52,43.02 8.88,42.38 5.08,42.38 5.08,41.74 CORE-IO.4
PIA-A4
  Bottom 0.254: IC25.6 8.25,43.02 9.52,41.74 9.52,39.84 4.44,39.84 3.17,38.57 CORE-IO.5
PIA-A5
  Top 0.254: IC25.7 6.98,40.48 5.71,39.2 5.71,38.57 CORE-IO.6
PIA-A6
  Bottom 0.254: IC25.8 6.98,37.94 6.34,37.3 4.44,37.3 3.17,36.03 CORE-IO.7
PIA-A7
  Top 0.254: IC25.9 6.34,36.03 5.71,36.03 CORE-IO.8
PIA-B0
  Bottom 0.254: IC26.2 6.98,26.5 6.34,27.14 4.44,27.14 3.17,28.41 CORE-IO.13
PIA-B1
  Top 0.254: IC26.3 6.98,22.7 6.34,22.7 5.71,22.06 4.44,22.06 3.81,22.7 3.81,26.5 5.08,27.77 CORE-IO.14
PIA-B2
  Bottom 0.254: IC26.4 6.98,20.15 6.34,19.52 4.44,19.52 3.81,20.15 3.81,25.23 2.54,25.23 CORE-IO.15
PIA-B3
  Top 0.254: IC26.5 8.25,18.88 9.52,20.15 9.52,23.96 8.88,24.6 5.08,24.6 5.08,25.23 CORE-IO.16
PIA-B4
  Top 0.254: IC26.6 8.25,15.08 9.52,13.81 9.52,7.46 8.88,6.82 4.44,6.82 4.44,19.52 3.81,20.15 3.81,21.42 2.54,22.7 CORE-IO.17
PIA-B5
  Bottom 0.254: IC26.7 8.25,13.81 9.52,15.08 9.52,22.06 5.71,22.06 5.08,22.7 CORE-IO.18
PIA-B6
  Bottom 0.254: IC26.8 6.98,11.27 2.54,15.71 2.54,20.15 CORE-IO.19
PIA-B7
  Top 0.254: IC26.9 6.98,8.73 5.08,10.63 5.08,20.15 CORE-IO.20
R/W\  (via drill 0.61)
  Top 0.254: v92.7,51.27 92.7,43.65 93.98,42.38 IC22.27 | 33.02,39.84 33.02,63.97 31.75,65.24 31.75,79.21 30.48,80.48 IC17.34 | 33.02,39.84 33.02,10.63 34.92,8.73 IC24.21 | v77.47,36.66 77.47,55.71 79.37,55.71 80.64,54.45 IC21.13 | 33.02,39.84 v32.38,39.84
  Bottom 0.254: v92.7,51.27 90.8,53.17 81.91,53.17 IC21.13 | v77.47,36.66 60.32,36.66 59.68,37.3 59.68,40.48 52.7,40.48 52.06,39.84 v32.38,39.84
RST\  (via drill 0.61)
  Top 0.254: v31.75,41.11 26.67,46.19 26.67,77.94 24.12,80.48 24.12,83.02 23.49,83.66 15.23,83.66 15.23,83.02 IC17.40 | v73.02,24.6 68.58,20.15 v68.58,16.98 | v38.73,17.61 37.46,18.88 37.46,39.2 36.19,40.48 IC24.34
  Bottom 0.254: v31.75,41.11 34.28,41.11 IC24.34 | v73.02,24.6 77.47,24.6 80.01,22.06 93.34,22.06 98.42,16.98 123.19,16.98 123.19,10 122.55,9.36 111.76,9.36 110.48,8.09 IC18.6 | v68.58,16.98 67.94,17.61 v38.73,17.61
RX
  Top 0.254: IC20.12 57.78,34.12 55.88,36.03 55.88,37.3 IC21.2
RXD
  Top 0.254: IC20.13 55.88,32.22 54.6,30.95 54.6,17.61 53.34,16.34 X1.3
TX
  Top 0.254: IC20.11 60.95,34.76 62.22,36.03 62.22,39.84 62.86,40.48 66.04,40.48 66.04,39.84 IC21.6
TXD  (via drill 0.61)
  Top 0.254: v55.88,30.95 57.14,29.68 57.14,16.98 56.51,16.34 X1.2
  Bottom 0.254: v55.88,30.95 53.97,32.85 IC20.14
VCC  (via drill 0.61)
  Top 0.508: IC24.22 34.92,11.27 33.65,12.54 33.65,13.81 34.92,15.08 IC24.24 | v48.25,38.57 48.25,34.76 IC20.16 | BYP20.1 43.17,21.42 43.17,22.7 C10.1 43.17,23.96 43.17,30.31 45.08,32.22 v45.08,32.85 45.08,47.46 45.71,48.09 R7.2 | R5.2 10.79,76.67 12.06,76.67 R8.2 | IC17.36 26.03,81.11 27.3,81.11 IC17.35 | IC26.20 15.23,29.04 15.23,30.31 BYP26.1 | IC25.20 15.23,56.98 15.23,58.25 BYP25.1 | 67.31,84.29 67.94,84.29 IC28.16 | 67.31,84.29 66.67,84.29 BYP28.1 | 67.31,84.29 67.31,74.13 68.58,72.86 IC19.16 | BYP29.1 89.53,81.75 90.8,81.75 IC29.28 91.44,80.48 91.44,67.78 IC29.1 91.44,65.24 91.44,62.7 IC23.28 91.44,60.16 91.44,47.46 IC23.1 91.44,44.92 91.44,42.38 IC22.28 | v99.69,10.63 99.06,11.27 99.06,17.61 R2.2 99.06,18.88 99.06,20.15 R1.2 99.69,20.79 101.59,22.7 BYP17.1 | 88.26,10.63 88.26,6.82 85.72,6.82 84.45,5.55 R9.2 | 88.26,10.63 R3.2 88.26,10.63 | 88.26,10.63 86.99,10.63 R12.2 85.72,10.63 85.72,11.27 84.45,12.54 IC27.10 83.18,13.81 81.91,15.08 81.91,28.41 | R6.2 86.36,50.63 88.9,48.09 88.9,41.74 BYP22.1 | IC27.14 83.81,23.96 83.81,25.23 BYP27.1 83.81,26.5 81.91,28.41 | 81.91,28.41 81.28,29.04 81.28,37.3 IC21.12
  Bottom 0.508: R14.2 17.78,6.18 19.05,7.46 19.68,7.46 IC24.20 21.59,8.09 24.12,10.63 34.28,10.63 IC24.22 | v48.25,38.57 50.16,38.57 BYP21.1 | v45.08,32.85 47.62,32.85 IC20.16 | 33.65,19.52 33.65,17.61 34.92,16.34 IC24.24 | 33.65,19.52 41.27,19.52 42.54,20.79 BYP20.1 43.81,20.79 46.35,18.25 70.48,18.25 73.02,15.71 74.93,15.71 IC27.4 77.47,15.71 80.01,13.17 82.55,13.17 IC27.10 | 19.05,78.58 22.22,78.58 24.76,81.11 IC17.36 | 19.05,78.58 15.23,78.58 13.33,76.67 R8.2 | 3.17,32.22 2.54,32.85 CORE-IO.9 | 3.17,32.22 4.44,30.95 CORE-IO.12 | 13.33,32.22 14.6,30.95 BYP26.1 | 13.33,32.22 3.17,32.22 | BYP24.1 24.76,58.89 23.49,57.62 17.78,57.62 16.51,56.35 IC25.20 13.96,56.35 13.33,56.35 13.33,32.22 | 15.23,62.06 8.25,62.06 JP4.2 | 15.23,62.06 19.05,62.06 | 19.05,62.06 28.57,62.06 32.38,65.88 IC17.8 | 15.23,62.06 15.23,59.52 BYP25.1 | 19.05,62.06 19.05,78.58 | 33.65,19.52 23.49,29.68 17.78,29.68 16.51,28.41 IC26.20 | BYP19.1 66.67,71.59 67.94,71.59 IC19.16 | IC23.27 93.34,60.8 92.07,60.8 IC23.28 90.8,61.43 86.99,61.43 BYP23.1 85.72,61.43 79.37,61.43 78.73,60.8 59.05,60.8 56.51,58.25 JP2.2 | IC28.16 69.21,83.66 70.48,82.39 88.9,82.39 BYP29.1 | v99.69,10.63 106.04,10.63 BYP18.1 | IC18.14 115.56,20.79 114.3,22.06 103.5,22.06 102.23,23.33 BYP17.1 | IC22.28 90.8,41.11 89.53,41.11 BYP22.1 88.26,41.11 87.62,40.48 79.37,40.48 | 74.29,40.48 73.02,40.48 71.75,39.2 IC21.8 | 74.29,40.48 75.56,39.2 IC21.10 | 79.37,40.48 80.64,39.2 IC21.12 | 79.37,40.48 74.29,40.48 | R1.2 98.42,20.79 95.88,23.33 85.09,23.33 IC27.14
VMA  (via drill 0.61)
  Top 0.254: v37.46,69.69 39.36,67.78 39.36,61.43 40,60.8 v40,32.85
  Bottom 0.254: v37.46,69.69 28.57,69.69 26.03,67.14 IC17.5 | v40,32.85 43.17,29.68 47.62,29.68 48.25,30.31 52.7,30.31 53.34,29.68 66.67,29.68 67.94,30.95 78.1,30.95 80.64,28.41 124.45,28.41 125.73,27.14 125.73,8.73 117.47,8.73 IC18.9

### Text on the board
Top: Component Side
Bottom: Solder side | PA8PDP/VRS
tPlace: RealConsole CORE - Rev.1 | +
tValues: - | +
